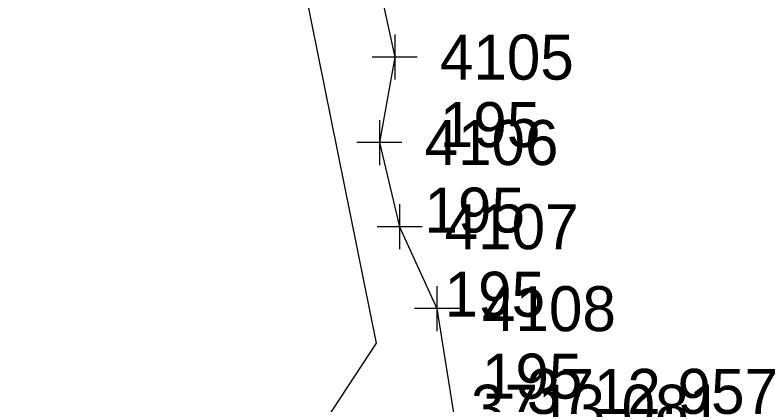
# Model space of a CAD drawing. Extents: x 352921 to 392463, y 10654752 to 10749237.
# Drawn here: x 385296.1 to 385379.5, y 10655195.7 to 10655239 of the extents above; entities that cross this region are included whole.
import ezdxf

# ---------------------------------------------------------------- set-up
doc = ezdxf.new("R2010")
doc.units = 0
for name, color, linetype in [('LIMITS', 7, 'Continuous'), ('TELE', 7, 'Continuous'), ('TELE_#', 7, 'Continuous'), ('TELE_DES', 7, 'Continuous'), ('TELE_SPOT', 7, 'Continuous'), ('W_ELEV', 7, 'Continuous')]:
    doc.layers.add(name, color=color, linetype=linetype)

msp = doc.modelspace()

# ---------------------------------------------------------------- linework, layer by layer
at = {"layer": 'LIMITS'}
msp.add_lwpolyline([(385316.836, 10655172.952), (385336.238, 10655202.514), (385296.084, 10655401.301), (385364.419, 10655416.325), (385383.945, 10655326.238), (385639.033, 10655377.812), (385628.063, 10655457.521), (385689.37, 10655471.818), (385708.029, 10655388.945), (385758.431, 10655397.426), (385771.759, 10655335.877), (385725.234, 10655328.365), (385738.807, 10655269.608), (386184.565, 10655359.732)], dxfattribs=at)
at = {"layer": 'TELE'}
msp.add_lwpolyline([(385316.04, 10655338.112), (385320.176, 10655319.793), (385323.509, 10655303.838), (385332.844, 10655259.106), (385338.253, 10655234.317), (385336.546, 10655224.825), (385338.78, 10655215.473), (385342.927, 10655206.363), (385345.06, 10655192.944), (385344.444, 10655182.793), (385341.809, 10655175.009), (385340.485, 10655172.818)], dxfattribs=at)
at = {"layer": 'TELE_SPOT'}
for p, q in [((385338.253, 10655236.817), (385338.253, 10655231.817)), ((385340.753, 10655234.317), (385335.753, 10655234.317)), ((385336.546, 10655227.325), (385336.546, 10655222.325)), ((385339.046, 10655224.825), (385334.046, 10655224.825)), ((385338.78, 10655217.973), (385338.78, 10655212.973)), ((385341.28, 10655215.473), (385336.28, 10655215.473)), ((385342.927, 10655208.863), (385342.927, 10655203.863)), ((385345.427, 10655206.363), (385340.427, 10655206.363))]:
    msp.add_line(p, q, dxfattribs=at)

# ---------------------------------------------------------------- texts
at = {"layer": 'TELE_#'}
for s, p in [('4105', (385343.253, 10655231.817)), ('4106', (385341.546, 10655222.325)), ('4107', (385343.78, 10655212.973)), ('4108', (385347.927, 10655203.863))]:
    msp.add_text(s, height=5, dxfattribs=at).set_placement(p)
at = {"layer": 'TELE_DES'}
for p in [(385343.253, 10655224.317), (385341.546, 10655214.825), (385343.78, 10655205.473), (385347.927, 10655196.363)]:
    msp.add_text('195', height=5, dxfattribs=at).set_placement(p)
at = {"layer": 'W_ELEV'}
for s, p in [('3712.957', (385352.917, 10655194.672)), ('3713.081', (385346.706, 10655192.911))]:
    msp.add_text(s, height=5, dxfattribs=at).set_placement(p)

doc.saveas('drawing.dxf')
